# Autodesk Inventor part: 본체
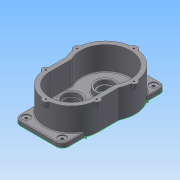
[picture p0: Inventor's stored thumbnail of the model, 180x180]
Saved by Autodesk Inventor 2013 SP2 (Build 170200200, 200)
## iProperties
Created: 2025-09
Part Number: 본체
Material: Generic
Document SubType Name: Modeling
Designer: a
Density: 1 g/cm^3
Author: a
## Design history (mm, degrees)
sketch "스케치5"
  geometry: L1 (-78, 60)-(-29.816, 60); L2 (-78, -60)-(-29.816, -60); A1 r 67 centre (0, 0) between (-44.699, 49.91) and (-29.816, -60); A2 r 60 centre (-78, 0) between (-78, -60) and (-78, 60); A3 r 60 centre (-78, 0) between (-78, 60) and (-78, -60); A4 r 67 centre (0, 0) between (-29.816, 60) and (-44.699, 49.91); A5 r 67 centre (0, 0) between (-29.816, -60) and (-29.816, 60); 1 further point
  constraints: 11 point on circle, 5 centre point, 4 end point, 2 tangent, 1 coincident, 1 horizontal, 1 horizontal alignment, 1 parallel
  dimensions: "d27" = 134 diameter of A1; "d28" = 120 diameter of A2; "d29" = 78 distance of A2.centre point (0, 0)
extrude "돌출3" new body sketch "스케치5" distance "d30" = 64; taper "d31" = 0 deg
sketch "스케치6"
  geometry: L1 (-83, -55)-(154, -55); L2 (154, -55)-(154, 55); L3 (154, 55)-(-83, 55); L4 (-83, 55)-(-83, -55); A1 r 67 centre (0, 0) between (29.816, 60) and (29.816, -60) reference; A2 r 60 centre (78, 0) between (78, -60) and (78, 60) reference; 1 further point
  constraints: 8 end point, 2 parallel, 1 horizontal, 1 horizontal alignment, 1 midpoint, 1 perpendicular
  dimensions: "d33" = 76 horizontal distance of L2.end A2.centre; "d34" = 237 distance of L2.end L3.end; "d35" = 110 distance of L1.end L2.end
extrude "돌출4" join sketch "스케치6" distance "d36" = 10; taper "d37" = 0 deg
sketch "스케치7" dims "d55" = 0
  geometry: L1 (154, 10)-(154, 0) reference; L2 (154, 0)-(-83, 0) reference; L3 (-83, 0)-(-83, 10) reference; L4 (-83, 10)-(-67, 10) reference; L5 (-67, 10)-(-67, 64) reference; L6 (-67, 64)-(138, 64) reference; L7 (138, 64)-(138, 10) reference; L8 (138, 10)-(154, 10) reference; L9 (0, 0)-(0, 64); L10 (-57, 64)-(-57, 10); L11 (-57, 10)-(-23.5, 10); L12 (154, 10)-(154, 0) reference; L13 (154, 0)-(-83, 0) reference; L14 (-83, 0)-(-83, 10) reference; L15 (-83, 10)-(-67, 10) reference; L16 (138, 10)-(154, 10) reference; L17 (-23.5, 10)-(-23.5, 22); L18 (-23.5, 22)-(-19.5, 22); L19 (-18.5, 21)-(-18.5, 13.3); L20 (-18.2, 13)-(-15, 13); L21 (-15, 13)-(-15, 8.3); L22 (-15, 8.3)-(-17.2, 8.3); L23 (-57, 64)-(0, 64); L24 (-17.5, 8)-(-17.5, 0.8); L25 (-17.5, 0.8)-(-17.962, 0); L26 (-17.962, 0)-(0, 0); L27 (-67, 10)-(-67, 64) reference; L28 (-67, 64)-(138, 64) reference; L29 (138, 64)-(138, 10) reference; L30 (-18.5, 21)-(-19.5, 22); A1 r 0.3 centre (-18.2, 13.3) between (-18.5, 13.3) and (-18.2, 13); A2 r 0.3 centre (-17.2, 8) between (-17.2, 8.3) and (-17.5, 8); 5 further points
  constraints: 28 end point, 7 point on line, 5 parallel, 5 perpendicular, 4 point on circle, 4 tangent, 2 centre point, 2 collinear, 2 horizontal, 2 horizontal alignment, 2 vertical, 8 other
  dimensions: "d39" = 114 diameter of L10 L9; "d41" = 42 distance between parallel lines of L23 L18; "d43" = 7.5 distance of point (-17.5, 8.3) L24.end; "d44" = 35 diameter of L24 L9; "d45" = 0.8 distance from line of L13 L24.end; "d46" = 30 deg angle of L24 L25; "d47" = 30 diameter of L21 L9; "d48" = 9 distance of point (-18.5, 22) point (-18.5, 13); "d49" = 37 diameter of L19 L9; "d50" = 47 diameter of L17 L9; "d51" = 10 distance between parallel lines of L2 L11; "d52" = 0.3 radius of A1; "d53" = 1 distance of L19.start point (-18.5, 22); "d54" = 1 distance of L18.end point (-18.5, 22) (= d53); "d149" = 0.3 radius of A2
revolve "회전1" sketch "스케치7" stored, may be unused: angle "d56" = 90 deg
sketch "스케치8" dims "d67" = 0
  geometry: L1 (138, 10)-(154, 10) reference; L2 (154, 10)-(154, 0) reference; L3 (154, 0)-(17.962, 0) reference; L4 (17.962, 0)-(17.5, 0.8) reference; L5 (17.5, 0.8)-(17.5, 8) reference; L6 (17.2, 8.3)-(15, 8.3) reference; L7 (15, 8.3)-(15, 13) reference; L8 (15, 13)-(18.2, 13) reference; L9 (18.5, 13.3)-(18.5, 21) reference; L10 (18.5, 21)-(19.5, 22) reference; L11 (19.5, 22)-(23.5, 22) reference; L12 (23.5, 22)-(23.5, 10) reference; L13 (23.5, 10)-(57, 10) reference; L14 (57, 10)-(57, 64) reference; L15 (57, 64)-(138, 64) reference; L16 (138, 64)-(138, 10) reference; L17 (-83, 10)-(-67, 10) reference; L18 (-67, 10)-(-67, 64) reference; L19 (-67, 64)-(-57, 64) reference; L20 (-57, 64)-(-57, 10) reference; L21 (-57, 10)-(-23.5, 10) reference; L22 (-23.5, 10)-(-23.5, 22) reference; L23 (-23.5, 22)-(-19.5, 22) reference; L24 (-19.5, 22)-(-18.5, 21) reference; L25 (-18.5, 21)-(-18.5, 13.3) reference; L26 (-18.2, 13)-(-15, 13) reference; L27 (-15, 13)-(-15, 8.3) reference; L28 (-15, 8.3)-(-17.2, 8.3) reference; L29 (-17.5, 8)-(-17.5, 0.8) reference; L30 (-17.5, 0.8)-(-17.962, 0) reference; L31 (-17.962, 0)-(-83, 0) reference; L32 (-83, 0)-(-83, 10) reference; L33 (78, 0)-(78, 64); L34 (78, 64)-(128, 64); L35 (128, 64)-(128, 10); L36 (128, 10)-(101.5, 10); L37 (101.5, 10)-(101.5, 36); L38 (101.5, 36)-(97.5, 36); L39 (96.5, 35)-(96.5, 27.3); L40 (96.2, 27)-(94, 27); L41 (94, 27)-(94, 11); L42 (94, 11)-(93, 11); L43 (92, 10)-(92, 8.3); L44 (91.7, 8)-(78, 8); L45 (96.5, 35)-(97.5, 36); L46 (92, 10)-(93, 11); A1 r 0.3 centre (18.2, 13.3) between (18.2, 13) and (18.5, 13.3) reference; A2 r 0.3 centre (-18.2, 13.3) between (-18.5, 13.3) and (-18.2, 13) reference; A3 r 0.3 centre (96.2, 27.3) between (96.2, 27) and (96.5, 27.3); A4 r 0.3 centre (91.7, 8.3) between (91.7, 8) and (92, 8.3); A5 r 0.3 centre (17.2, 8) between (17.5, 8) and (17.2, 8.3) reference; A6 r 0.3 centre (-17.2, 8) between (-17.2, 8.3) and (-17.5, 8) reference; 7 further points
  constraints: 28 end point, 12 point on line, 7 parallel, 4 perpendicular, 4 point on circle, 4 tangent, 2 centre point, 2 horizontal, 2 vertical, 1 equal radius, 8 other
  dimensions: "d57" = 76 distance from line of L33 L2.end; "d58" = 3 distance of point (92, 11) point (92, 8); "d59" = 16 distance of L40.end L41.end; "d60" = 9 distance of point (96.5, 36) point (96.5, 27); "d61" = 28 distance between parallel lines of L38 L15; "d62" = 28 diameter of L43 L33; "d63" = 32 diameter of L41 L33; "d64" = 47 diameter of L37.end L33; "d65" = 100 diameter of L35 L33; "d66" = 10 distance between parallel lines of L3 L36; "d68" = 37 diameter of L39 L33; "d69" = 1 distance of L39.start point (96.5, 36); "d70" = 1 distance of L38.end point (96.5, 36) (= d69); "d71" = 0.3 radius of A3; "d72" = 1 distance of L43.start point (92, 11); "d73" = 1 distance of L42.end point (92, 11) (= d72)
revolve "회전2" sketch "스케치8" stored, may be unused: angle "d74" = 90 deg
node "작업 평면1"
sketch "스케치11"
  geometry: L1 (-37.5, -51.159)-(-37.5, 51.159); L2 (-37.5, 51.159)-(-22.5, 51.159); L3 (-22.5, 51.159)-(-22.5, -51.159); L4 (-22.5, -51.159)-(-37.5, -51.159); L5 (0, 55)-(0, -55) reference; 5 further points
  constraints: 4 midpoint, 2 horizontal alignment, 1 vertical alignment, 2 other
  dimensions: "d79" = 15 distance of L3.end L1.start; "d81" = 30 distance from line of L5 point (-30, -51.159)
feature "엠보싱1" sketch "스케치11" dims "d82" = 0.5, "d83" = 0
sketch "스케치12"
  geometry: L1 (78, 60)-(29.816, 60) reference; L2 (78, -50)-(27.368, -50); L3 (78, 50)-(27.368, 50); A1 r 50 centre (78, 0) between (43.801, -36.475) and (43.801, 36.475) reference; A2 r 57 centre (0, 0) between (43.801, 36.475) and (43.801, -36.475) reference
  constraints: 4 end point, 4 point on circle, 2 parallel, 2 tangent
extrude "돌출6" cut sketch "스케치12" distance "d84" = 54; taper "d85" = 0 deg
sketch "스케치13"
  geometry: C1 r 19.5 at (0, 0) reference; C2 r 23.5 at (0, 0); A1 r 57 centre (-78, 0) between (-21.713, -8.988) and (-21.713, 8.988) reference; A2 r 23.5 centre (0, 0) between (-21.713, -8.988) and (-21.713, 8.988) reference
  constraints: 1 centre point, 1 coincident, 1 concentric
extrude "돌출7" join sketch "스케치13" distance "d86" = 54; taper "d87" = 0 deg
sketch "스케치14"
  geometry: L1 (27.368, -50)-(78, -50) reference; L2 (78, 50)-(27.368, 50) reference; L3 (78, -60)-(29.816, -60) reference; L4 (29.816, 60)-(78, 60) reference; C1 r 8 at (78, -58); C2 r 8 at (78, 58); C3 r 8 at (136, 0); C4 r 8 at (0, -65); C5 r 8 at (0, 65); C6 r 8 at (-65, 0); A1 r 50 centre (78, 0) between (78, -50) and (78, 50) reference; A2 r 57 centre (0, 0) between (27.368, 50) and (27.368, -50) reference; A3 r 60 centre (78, 0) between (78, -60) and (78, 60) reference; A4 r 67 centre (0, 0) between (29.816, 60) and (29.816, -60) reference; 2 further points
  constraints: 6 centre point, 4 vertical alignment, 2 horizontal alignment
  dimensions: "d126" = 16 diameter of C1; "d127" = 58 distance of point (78, 0) C1.centre; "d128" = 16 diameter of C2; "d129" = 116 distance of C2.centre C1.centre; "d130" = 16 diameter of C3; "d131" = 58 distance of point (78, 0) C3.centre; "d132" = 16 diameter of C4; "d133" = 65 distance of C4.centre A2.centre; "d134" = 16 diameter of C5; "d135" = 130 distance of C5.centre C4.centre; "d136" = 16 diameter of C6; "d137" = 65 distance of C6.centre A2.centre
extrude "돌출8" join sketch "스케치14" distance "d96" = 12; taper "d97" = 0 deg
fillet "모깎기1" dims "d105" = 14
sketch "스케치16"
  geometry: A1 r 14 centre (-69, -41) between (-83, -41) and (-69, -55) reference; A2 r 67 centre (0, 0) between (-38.262, 55) and (-38.262, -55) reference; A3 r 14 centre (-69, 41) between (-69, 55) and (-83, 41) reference; 2 further points
  dimensions: "d106" = 209 distance of point (140, 41) A3.centre; "d107" = 209 distance of A1.centre point (140, -41); "d109" = 41 vertical distance of point (140, 41) A2.centre; "d110" = 82 distance of point (140, 41) point (140, -41)
hole "구멍2" sketch "스케치16" at (140, 41), (140, -41), (-69, 41), (-69, -41) diameter "d111" = 6.6; stored, may be unused: countersink angle "d115" = 90 deg, drill point angle "d117" = 118 deg; dims "d112" = 8, "d113" = 18, "d114" = 2, "d116" = 10
fillet "모깎기2" dims "d118" = 2
fillet "모깎기6" dims "d122" = 2
fillet "모깎기7" dims "d123" = 2
sketch "스케치17"
  geometry: L1 (-83, 41)-(-83, -41) reference; L2 (-69, -55)-(-38.884, -55) reference; L3 (29.816, -60)-(78, -60) reference; L4 (102.393, -55)-(140, -55) reference; L5 (154, -41)-(154, 41) reference; L6 (140, 55)-(102.393, 55) reference; L7 (78, 60)-(29.816, 60) reference; L8 (-38.884, 55)-(-69, 55) reference; C1 r 3.3 at (-69, -41) reference; C2 r 3.3 at (140, -41) reference; C3 r 3.3 at (140, 41) reference; C4 r 3.3 at (-69, 41) reference; C5 r 17.962 at (0, 0) reference; A1 r 57 centre (0, 0) between (56.287, -8.988) and (56.287, 8.988) reference; A2 r 23.5 centre (78, 0) between (56.287, 8.988) and (56.287, -8.988) reference; A3 r 14 centre (-69, 41) between (-69, 55) and (-83, 41) reference; A4 r 14 centre (-69, -41) between (-83, -41) and (-69, -55) reference; A5 r 2 centre (-38.884, -57) between (-37.757, -55.348) and (-38.884, -55) reference; A6 r 67 centre (0, 0) between (-37.757, -55.348) and (29.816, -60) reference; A7 r 60 centre (78, 0) between (78, -60) and (101.606, -55.161) reference; A8 r 2 centre (102.393, -57) between (102.393, -55) and (101.606, -55.161) reference; A9 r 14 centre (140, -41) between (140, -55) and (154, -41) reference; A10 r 14 centre (140, 41) between (154, 41) and (140, 55) reference; A11 r 2 centre (102.393, 57) between (101.606, 55.161) and (102.393, 55) reference; A12 r 60 centre (78, 0) between (101.606, 55.161) and (78, 60) reference; A13 r 67 centre (0, 0) between (29.816, 60) and (-37.757, 55.348) reference; A14 r 2 centre (-38.884, 57) between (-38.884, 55) and (-37.757, 55.348) reference
sketch "스케치18"
  geometry: L1 (82, 0)-(0, 0); L2 (0, 0)-(0, -18); L3 (0, -18)-(82, -18); L4 (82, -18)-(82, 0); L5 (32.012, -18)-(49.988, -18) reference; 2 further points
  constraints: 8 end point, 2 parallel, 1 horizontal, 1 perpendicular, 1 point on line, 1 vertical alignment
extrude "돌출9" cut sketch "스케치18" stored distance "d124" = 10; taper "d125" = 0 deg
sketch "스케치19"
  geometry: A1 r 8 centre (-65, 0) between (-66.538, 7.851) and (-66.538, -7.851) reference; A2 r 8 centre (0, -65) between (-7.851, -66.538) and (7.851, -66.538) reference; A3 r 8 centre (78, -58) between (70.254, -60) and (85.861, -59.483) reference; A4 r 8 centre (136, 0) between (137.483, -7.861) and (137.483, 7.861) reference; A5 r 8 centre (78, 58) between (85.861, 59.483) and (70.254, 60) reference; A6 r 8 centre (0, 65) between (7.851, 66.538) and (-7.851, 66.538) reference
hole "구멍3" sketch "스케치19" at (0, 65), (-65, 0), (0, -65), (78, 58), (136, 0), (78, -58) diameter "d138" = 3.242; stored, may be unused: countersink angle "d142" = 90 deg, drill point angle "d144" = 118 deg; dims "d139" = 8, "d140" = 4, "d141" = 2, "d143" = 10
fillet "모깎기8" dims "d145" = 2
fillet "모깎기9" dims "d146" = 2
fillet "모깎기10" dims "d147" = 13
fillet "모깎기11" dims "d148" = 2
node "솔리드2"
node "절단 모서리 투영5"
node "절단 모서리 투영6"
node "절단 모서리 투영7"
node "절단 모서리 투영8"
